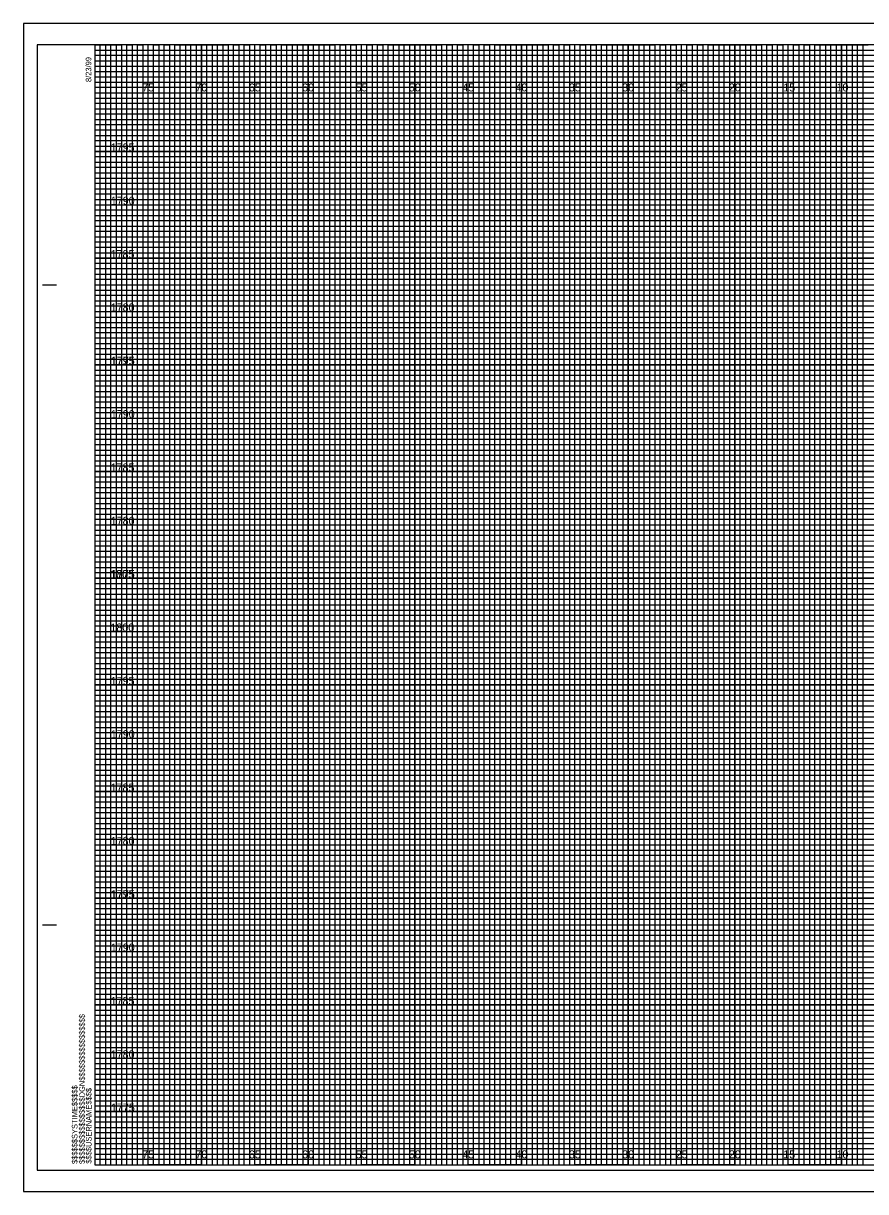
# Model space of a CAD drawing. Extents: x -7 to 162, y -2 to 107.
# Drawn here: x -6.7 to 72.2, y -2.5 to 107 of the extents above; entities that cross this region are included whole.
import ezdxf

# ---------------------------------------------------------------- set-up
doc = ezdxf.new("R2010")
doc.units = 0
for name, color, linetype in [('Exist Cross Section Cell', 7, 'Continuous'), ('Exist XS Center Line Elevation Label', 7, 'Continuous'), ('Exist XS Ground Line', 7, 'Continuous'), ('Prop XS Ditch Standard Text', 7, 'Continuous'), ('Prop XS Dump Level', 7, 'Continuous'), ('Prop XS Finish Grade', 7, 'Continuous'), ('Prop XS Finish Grade Earthwork', 7, 'Continuous'), ('Prop XS SE Text', 7, 'Continuous'), ('Prop XS Side Slope Text', 7, 'Continuous'), ('Prop XS SS Elevation Text', 7, 'Continuous'), ('Prop XS Subgrade Earthwork', 7, 'Continuous')]:
    doc.layers.add(name, color=color, linetype=linetype)

msp = doc.modelspace()

# ---------------------------------------------------------------- linework, layer by layer
at = {"layer": 'Exist XS Center Line Elevation Label'}
for points in [[(0, 105), (2.5, 105), (2.5, 0), (7.5, 0), (7.5, 105), (12.5, 105), (12.5, 0), (17.5, 0), (17.5, 105), (22.5, 105), (22.5, 0), (27.5, 0), (27.5, 105), (32.5, 105), (32.5, 0), (37.5, 0), (37.5, 105), (42.5, 105), (42.5, 0), (47.5, 0), (47.5, 105), (52.5, 105), (52.5, 0), (57.5, 0), (57.5, 105), (62.5, 105), (62.5, 0), (67.5, 0), (67.5, 105), (72.5, 105)], [(0, 102.5), (137.5, 102.5)], [(0, 92.5), (160, 92.5), (160, 97.5), (0, 97.5)], [(0, 82.5), (160, 82.5), (160, 87.5), (0, 87.5)], [(0, 72.5), (160, 72.5), (160, 77.5), (0, 77.5)], [(0, 62.5), (160, 62.5), (160, 67.5), (0, 67.5)], [(0, 52.5), (160, 52.5), (160, 57.5), (0, 57.5)], [(0, 42.5), (160, 42.5), (160, 47.5), (0, 47.5)], [(0, 32.5), (160, 32.5), (160, 37.5), (0, 37.5)], [(0, 22.5), (160, 22.5), (160, 27.5), (0, 27.5)], [(0, 12.5), (160, 12.5), (160, 17.5), (0, 17.5)], [(0, 2.5), (160, 2.5), (160, 7.5), (0, 7.5)]]:
    msp.add_lwpolyline(points, dxfattribs=at)
at = {"layer": 'Exist XS Ground Line'}
for p, q in [((5, 105), (0, 105)), ((5, 0), (5, 105)), ((15, 105), (10, 105)), ((10, 105), (10, 0)), ((15, 0), (15, 105)), ((25, 105), (20, 105)), ((20, 105), (20, 0)), ((25, 0), (25, 105)), ((35, 105), (30, 105)), ((30, 105), (30, 0)), ((35, 0), (35, 105)), ((45, 105), (40, 105)), ((40, 105), (40, 0)), ((45, 0), (45, 105)), ((55, 105), (50, 105)), ((50, 105), (50, 0)), ((55, 0), (55, 105)), ((65, 105), (60, 105)), ((60, 105), (60, 0)), ((65, 0), (65, 105)), ((75, 105), (70, 105)), ((70, 105), (70, 0)), ((10, 0), (5, 0)), ((20, 0), (15, 0)), ((30, 0), (25, 0)), ((40, 0), (35, 0)), ((50, 0), (45, 0)), ((60, 0), (55, 0)), ((70, 0), (65, 0))]:
    msp.add_line(p, q, dxfattribs=at)
for points in [[(0, 100), (160, 100), (160, 95), (0, 95)], [(0, 90), (160, 90), (160, 85), (0, 85)], [(0, 80), (160, 80), (160, 75), (0, 75)], [(0, 70), (160, 70), (160, 65), (0, 65)], [(0, 60), (160, 60), (160, 55), (0, 55)], [(0, 50), (160, 50), (160, 45), (0, 45)], [(0, 40), (160, 40), (160, 35), (0, 35)], [(0, 30), (160, 30), (160, 25), (0, 25)], [(0, 20), (160, 20), (160, 15), (0, 15)], [(0, 10), (160, 10), (160, 5), (0, 5)]]:
    msp.add_lwpolyline(points, dxfattribs=at)
at = {"layer": 'Prop XS Ditch Standard Text'}
for points in [[(0, 0), (0.5, 0), (0.5, 105), (1, 105), (1, 0)], [(1, 0), (1.5, 0), (1.5, 105), (2, 105), (2, 0)], [(2.5, 0), (3, 0), (3, 105), (3.5, 105), (3.5, 0)], [(3.5, 0), (4, 0), (4, 105), (4.5, 105), (4.5, 0)], [(5, 0), (5.5, 0), (5.5, 105), (6, 105), (6, 0)], [(6, 0), (6.5, 0), (6.5, 105), (7, 105), (7, 0)], [(7.5, 0), (8, 0), (8, 105), (8.5, 105), (8.5, 0)], [(8.5, 0), (9, 0), (9, 105), (9.5, 105), (9.5, 0)], [(10, 0), (10.5, 0), (10.5, 105), (11, 105), (11, 0)], [(11, 0), (11.5, 0), (11.5, 105), (12, 105), (12, 0)], [(12.5, 0), (13, 0), (13, 105), (13.5, 105), (13.5, 0)], [(13.5, 0), (14, 0), (14, 105), (14.5, 105), (14.5, 0)], [(15, 0), (15.5, 0), (15.5, 105), (16, 105), (16, 0)], [(16, 0), (16.5, 0), (16.5, 105), (17, 105), (17, 0)], [(17.5, 0), (18, 0), (18, 105), (18.5, 105), (18.5, 0)], [(18.5, 0), (19, 0), (19, 105), (19.5, 105), (19.5, 0)], [(20, 0), (20.5, 0), (20.5, 105), (21, 105), (21, 0)], [(21, 0), (21.5, 0), (21.5, 105), (22, 105), (22, 0)], [(22.5, 0), (23, 0), (23, 105), (23.5, 105), (23.5, 0)], [(23.5, 0), (24, 0), (24, 105), (24.5, 105), (24.5, 0)], [(25, 0), (25.5, 0), (25.5, 105), (26, 105), (26, 0)], [(26, 0), (26.5, 0), (26.5, 105), (27, 105), (27, 0)], [(27.5, 0), (28, 0), (28, 105), (28.5, 105), (28.5, 0)], [(28.5, 0), (29, 0), (29, 105), (29.5, 105), (29.5, 0)], [(30, 0), (30.5, 0), (30.5, 105), (31, 105), (31, 0)], [(31, 0), (31.5, 0), (31.5, 105), (32, 105), (32, 0)], [(32.5, 0), (33, 0), (33, 105), (33.5, 105), (33.5, 0)], [(33.5, 0), (34, 0), (34, 105), (34.5, 105), (34.5, 0)], [(35, 0), (35.5, 0), (35.5, 105), (36, 105), (36, 0)], [(36, 0), (36.5, 0), (36.5, 105), (37, 105), (37, 0)], [(37.5, 0), (38, 0), (38, 105), (38.5, 105), (38.5, 0)], [(38.5, 0), (39, 0), (39, 105), (39.5, 105), (39.5, 0)], [(40, 0), (40.5, 0), (40.5, 105), (41, 105), (41, 0)], [(41, 0), (41.5, 0), (41.5, 105), (42, 105), (42, 0)], [(42.5, 0), (43, 0), (43, 105), (43.5, 105), (43.5, 0)], [(43.5, 0), (44, 0), (44, 105), (44.5, 105), (44.5, 0)], [(45, 0), (45.5, 0), (45.5, 105), (46, 105), (46, 0)], [(46, 0), (46.5, 0), (46.5, 105), (47, 105), (47, 0)], [(47.5, 0), (48, 0), (48, 105), (48.5, 105), (48.5, 0)], [(48.5, 0), (49, 0), (49, 105), (49.5, 105), (49.5, 0)], [(50, 0), (50.5, 0), (50.5, 105), (51, 105), (51, 0)], [(51, 0), (51.5, 0), (51.5, 105), (52, 105), (52, 0)], [(52.5, 0), (53, 0), (53, 105), (53.5, 105), (53.5, 0)], [(53.5, 0), (54, 0), (54, 105), (54.5, 105), (54.5, 0)], [(55, 0), (55.5, 0), (55.5, 105), (56, 105), (56, 0)], [(56, 0), (56.5, 0), (56.5, 105), (57, 105), (57, 0)], [(57.5, 0), (58, 0), (58, 105), (58.5, 105), (58.5, 0)], [(58.5, 0), (59, 0), (59, 105), (59.5, 105), (59.5, 0)], [(60, 0), (60.5, 0), (60.5, 105), (61, 105), (61, 0)], [(61, 0), (61.5, 0), (61.5, 105), (62, 105), (62, 0)], [(62.5, 0), (63, 0), (63, 105), (63.5, 105), (63.5, 0)], [(63.5, 0), (64, 0), (64, 105), (64.5, 105), (64.5, 0)], [(65, 0), (65.5, 0), (65.5, 105), (66, 105), (66, 0)], [(66, 0), (66.5, 0), (66.5, 105), (67, 105), (67, 0)], [(67.5, 0), (68, 0), (68, 105), (68.5, 105), (68.5, 0)], [(68.5, 0), (69, 0), (69, 105), (69.5, 105), (69.5, 0)], [(70, 0), (70.5, 0), (70.5, 105), (71, 105), (71, 0)], [(71, 0), (71.5, 0), (71.5, 105), (72, 105), (72, 0)]]:
    msp.add_lwpolyline(points, dxfattribs=at)
at = {"layer": 'Prop XS Dump Level'}
for p, q in [((0, 104.5), (130, 104.5)), ((130, 103.99), (0, 103.99)), ((0, 103.99), (0, 103.5)), ((0, 103.5), (130, 103.5)), ((130, 102.95), (0, 102.95)), ((0, 102.95), (0, 102)), ((0, 102), (160, 102))]:
    msp.add_line(p, q, dxfattribs=at)
for points in [[(0, 101.5), (135, 101.5), (160, 101.5), (160, 101), (0, 101)], [(0, 100.5), (160, 100.5), (160, 99.5), (0, 99.5)], [(0, 99), (160, 99), (160, 98.5), (0, 98.49)], [(0, 98), (160, 98), (160, 97), (0, 97)], [(0, 96.5), (160, 96.5), (160, 96), (0, 96)], [(0, 95.5), (160, 95.5), (160, 94.5), (0, 94.5)], [(0, 94), (160, 94), (160, 93.5), (0, 93.5)], [(0, 93), (160, 93), (160, 92), (0, 92)], [(0, 91.5), (160, 91.5), (160, 91), (0, 91)], [(0, 90.5), (160, 90.5), (160, 89.5), (0, 89.5)], [(0, 89), (160, 89), (160, 88.5), (0, 88.5)], [(0, 88), (160, 88), (160, 86.98), (160, 86.5), (160, 86), (0, 86)], [(0, 87), (160, 87), (160, 86.5), (0, 86.5)], [(0, 85.5), (160, 85.5), (160, 84.5), (0, 84.52)], [(0, 84.52), (160, 84.5), (160, 84), (0, 84)], [(0, 83.5), (160, 83.5), (160, 83), (0, 83)], [(0, 82), (160, 82), (160, 81.5), (0, 81.5)], [(0, 81), (160, 81), (160, 80.5), (0, 80.5)], [(-0.04, 79.45), (160, 79.45), (160, 78.94), (-0.04, 78.94)], [(0, 78.5), (160, 78.5), (160, 78), (0, 78)], [(0, 77), (160, 77), (160, 76.5), (0, 76.5)], [(0, 76), (160, 76), (160, 75.5), (0, 75.5)], [(0, 74.5), (160, 74.5), (160, 74), (0, 74)], [(0, 73.5), (160, 73.5), (160, 73), (0, 73)], [(0, 72), (160, 72), (160, 71.5), (0, 71.5)], [(0, 71), (160, 71), (160, 70.5), (0, 70.5)], [(0, 69.5), (160, 69.5), (160, 68.99), (0, 69)], [(0, 68.5), (160, 68.5), (160, 68), (0, 68)], [(0, 67), (160, 67), (160, 66.5), (0, 66.5)], [(0, 66), (160, 66), (160, 65.5), (0, 65.5)], [(0, 64.5), (160, 64.5), (160, 64), (0, 64)], [(0, 63.5), (160, 63.5), (160, 63), (0, 63)], [(0, 62), (160, 62), (160, 61.5), (0, 61.5)], [(0, 61), (160, 61), (160, 60.5), (0, 60.5)], [(0, 59.5), (160, 59.5), (160, 59), (0, 59)], [(0, 58.5), (160.03, 58.45), (160, 58), (0, 58)], [(0, 57), (160, 57), (160, 56.5), (0, 56.5)], [(0, 56), (160, 56), (160, 55.5), (0, 55.5)], [(0, 54.5), (160, 54.5), (160, 54), (0, 54)], [(0, 53.5), (160, 53.5), (160, 53), (0, 53)], [(0, 52), (160, 52), (160, 51.5), (0, 51.5)], [(0, 51), (160, 51), (160, 50.5), (0, 50.5)], [(0, 49.5), (160, 49.5), (160, 49), (0, 49)], [(0, 48.5), (160, 48.5), (160, 48), (0, 48)], [(0, 47), (160, 47), (160, 46.5), (0, 46.5)], [(0, 46), (160, 46), (160, 45.5), (0, 45.5)], [(0, 44.5), (160, 44.5), (160, 44), (0, 44)], [(0, 43.5), (160, 43.5), (160, 43), (0, 43)], [(0, 42), (160, 42), (160, 41.5), (0, 41.5)], [(0, 41), (160, 41), (160, 40.5), (0, 40.5)], [(0, 39.5), (160, 39.5), (160, 38.99), (0, 39)], [(0, 38.5), (160, 38.5), (160, 38), (0, 38)], [(0, 37), (160, 37), (160, 36.5), (0, 36.5)], [(0, 36), (160, 36), (160, 35.5), (0, 35.5)], [(0, 34.5), (160, 34.5), (160, 34), (0, 34)], [(0, 33.5), (160, 33.5), (160, 33), (0, 33)], [(0, 32), (160, 32), (160, 31.5), (0, 31.5)], [(0, 31), (160, 31), (160, 30.5), (0, 30.5)], [(0, 29.5), (160, 29.5), (160, 29), (0, 29)], [(0, 28.5), (160.03, 28.46), (160, 28), (0, 28)], [(0, 27), (160, 27), (160, 26.5), (0, 26.5)], [(0, 26), (160, 26), (160, 25.5), (0, 25.5)], [(0, 24.5), (160, 24.5), (160, 24), (0, 24)], [(0, 23.5), (160, 23.5), (160, 23), (0, 23)], [(0, 22), (160, 22), (160, 21.5), (0, 21.5)], [(0, 21), (160, 21), (160, 20.5), (0, 20.5)], [(0, 19.5), (160, 19.5), (160, 19), (0, 19)], [(0, 18.5), (160, 18.5), (160, 18), (0, 18)], [(0, 17), (160, 17), (160, 16.5), (0, 16.5)], [(0, 16), (160, 16), (160, 15.5), (0, 15.5)], [(0, 14.5), (160, 14.5), (160, 14), (0, 14)], [(0, 13.5), (160, 13.5), (160, 13), (0, 13)], [(0, 12), (160, 12), (160, 11.5), (0, 11.5)], [(0, 11), (160, 11), (160, 10.5), (0, 10.5)], [(0, 9.5), (160, 9.5), (160, 9), (0, 9)], [(0, 8.5), (160, 8.5), (160, 8), (0, 8)], [(0, 7), (160, 7), (160, 6.5), (0, 6.5)], [(0, 6), (160, 6), (160, 5.5), (0, 5.5)], [(0, 4.5), (160, 4.5), (160, 4), (0, 4)], [(0, 3.5), (160, 3.5), (160, 3), (0, 3)], [(0, 2), (160, 2), (160, 1.5), (0, 1.5)], [(0, 1), (160, 1), (160, 0.5), (0, 0.5)]]:
    msp.add_lwpolyline(points, dxfattribs=at)
at = {"layer": 'Prop XS Finish Grade Earthwork'}
for p, q in [((5, 0), (5, 105)), ((10, 0), (10, 105)), ((15, 0), (15, 105)), ((20, 0), (20, 105)), ((25, 0), (25, 105)), ((30, 0), (30, 105)), ((35, 0), (35, 105)), ((40, 0), (40, 105)), ((45, 0), (45, 105)), ((50, 0), (50, 105)), ((55, 0), (55, 105)), ((60, 0), (60, 105)), ((65, 0), (65, 105)), ((70, 0), (70, 105)), ((0, 100), (160, 100)), ((0, 95), (160, 95)), ((0, 90), (160, 90)), ((0, 85), (160, 85)), ((0, 80), (160, 80)), ((0, 75), (160, 75)), ((0, 70), (160, 70)), ((0, 65), (160, 65)), ((0, 60), (160, 60)), ((0, 55), (160, 55)), ((0, 50), (160, 50)), ((0, 45), (160, 45)), ((0, 40), (160, 40)), ((0, 35), (160, 35)), ((0, 30), (160, 30)), ((0, 25), (160, 25)), ((0, 20), (160, 20)), ((0, 15), (160, 15)), ((0, 10), (160, 10)), ((0, 5), (160, 5))]:
    msp.add_line(p, q, dxfattribs=at)
at = {"layer": 'Prop XS SE Text'}
for p, q in [((-4.9, 82.5), (-3.65, 82.5)), ((-4.85, 82.5), (-3.6, 82.5)), ((-4.9, 22.5), (-3.65, 22.5)), ((-4.85, 22.5), (-3.6, 22.5)), ((0, 0), (0, 0)), ((0, 0), (0, 0)), ((0, 0), (0, 0)), ((0, 0), (0, 0)), ((0, 0), (0, 0)), ((0, 0), (0, 0)), ((0, 0), (0, 0))]:
    msp.add_line(p, q, dxfattribs=at)
msp.add_lwpolyline([(160, 105), (0, 105), (0, 0), (160, 0)], close=True, dxfattribs=at)
at = {"layer": 'Prop XS Side Slope Text'}
msp.add_lwpolyline([(-6.7, -2.5), (161.65, -2.5), (161.65, 107), (-6.7, 107)], close=True, dxfattribs=at)
at = {"layer": 'Prop XS SS Elevation Text'}
msp.add_lwpolyline([(-5.4, -0.5), (161.2, -0.5), (161.2, 105), (-5.4, 105)], close=True, dxfattribs=at)
at = {"layer": 'Prop XS Subgrade Earthwork'}
for p, q in [((161.65, 107), (-6.7, 107)), ((-6.7, 107), (-6.7, -2.5)), ((-6.7, -2.5), (161.65, -2.5))]:
    msp.add_line(p, q, dxfattribs=at)

# ---------------------------------------------------------------- texts
at = {"layer": 'Exist Cross Section Cell'}
for s, p in [('75', (4.44, 100.62)), ('70', (9.43, 100.62)), ('65', (14.44, 100.62)), ('60', (19.43, 100.62)), ('55', (24.44, 100.62)), ('50', (29.43, 100.62)), ('45', (34.44, 100.62)), ('40', (39.43, 100.62)), ('35', (44.44, 100.62)), ('30', (49.43, 100.62)), ('25', (54.44, 100.62)), ('20', (59.43, 100.62)), ('15', (64.53, 100.62)), ('10', (69.52, 100.62)), ('75', (4.44, 0.62)), ('70', (9.43, 0.62)), ('65', (14.44, 0.62)), ('60', (19.43, 0.62)), ('55', (24.44, 0.62)), ('50', (29.43, 0.62)), ('45', (34.44, 0.62)), ('40', (39.43, 0.62)), ('35', (44.44, 0.62)), ('30', (49.43, 0.62)), ('25', (54.44, 0.62)), ('20', (59.43, 0.62)), ('15', (64.53, 0.62)), ('10', (69.52, 0.62))]:
    msp.add_text(s, height=0.75, dxfattribs=at).set_placement(p)
at = {"layer": 'Prop XS Finish Grade'}
for s, p in [('1795', (1.49, 95)), ('1790', (1.5, 90)), ('1785', (1.48, 85)), ('1780', (1.49, 80)), ('1795', (1.49, 75)), ('1775', (1.51, 75)), ('1790', (1.5, 70)), ('1785', (1.48, 65)), ('1780', (1.49, 60)), ('1805', (1.45, 55)), ('1775', (1.51, 55)), ('1800', (1.46, 50)), ('1795', (1.49, 45)), ('1790', (1.5, 40)), ('1785', (1.48, 35)), ('1780', (1.49, 30)), ('1795', (1.49, 25)), ('1775', (1.51, 25)), ('1790', (1.5, 20)), ('1785', (1.48, 15)), ('1780', (1.49, 10)), ('1775', (1.51, 5))]:
    msp.add_text(s, height=0.75, dxfattribs=at).set_placement(p)
at = {"layer": 'Prop XS SE Text'}
for s, p in [('8/23/99', (-0.33, 101.5)), ('$$$$$$$$$$$$$$$$DGN$$$$$$$$$$$$$$$$', (-0.94, 0.09)), ('$$$$$$SYSTIME$$$$$', (-1.63, 0.09)), ('$$$$USERNAME$$$$', (-0.31, 0.12))]:
    msp.add_text(s, height=0.525, rotation=90, dxfattribs=at).set_placement(p)

doc.saveas('drawing.dxf')
